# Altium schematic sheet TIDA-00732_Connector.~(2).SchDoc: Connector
size 431 x 279 mm; Date: Not shown in title block; ApprovedBy: Not shown in title block; CheckedBy: Not shown in title block; Author: Not shown in title block; CompanyName: Not shown in title block; DrawnBy: Anbu Mani; Engineer: Not shown in title block; Organization: Not shown in title block; Address1: Not shown in title block; Address2: Not shown in title block; Address3: Not shown in title block; Address4: Not shown in title block; DocumentNumber: 1; Revision: Use project parameter SCH_Rev; SheetNumber: 2; SheetTotal: 10; PageSetup: Record=PageOptions¦CenterHorizontal=True¦CenterVertical=True¦PrintScale=1.00¦XCorrection=1.00¦YCorrection=1.00¦PrintKind=0¦BorderSize=5000000¦LeftOffset=0¦BottomOffset=0¦Orientation=2¦PaperLength=1000¦PaperWidth=1000¦Scale=100¦PaperSource=15¦PrintQuality=600¦MediaType=1¦DitherType=10¦PaperKind=Letter¦PrintScaleMode=1
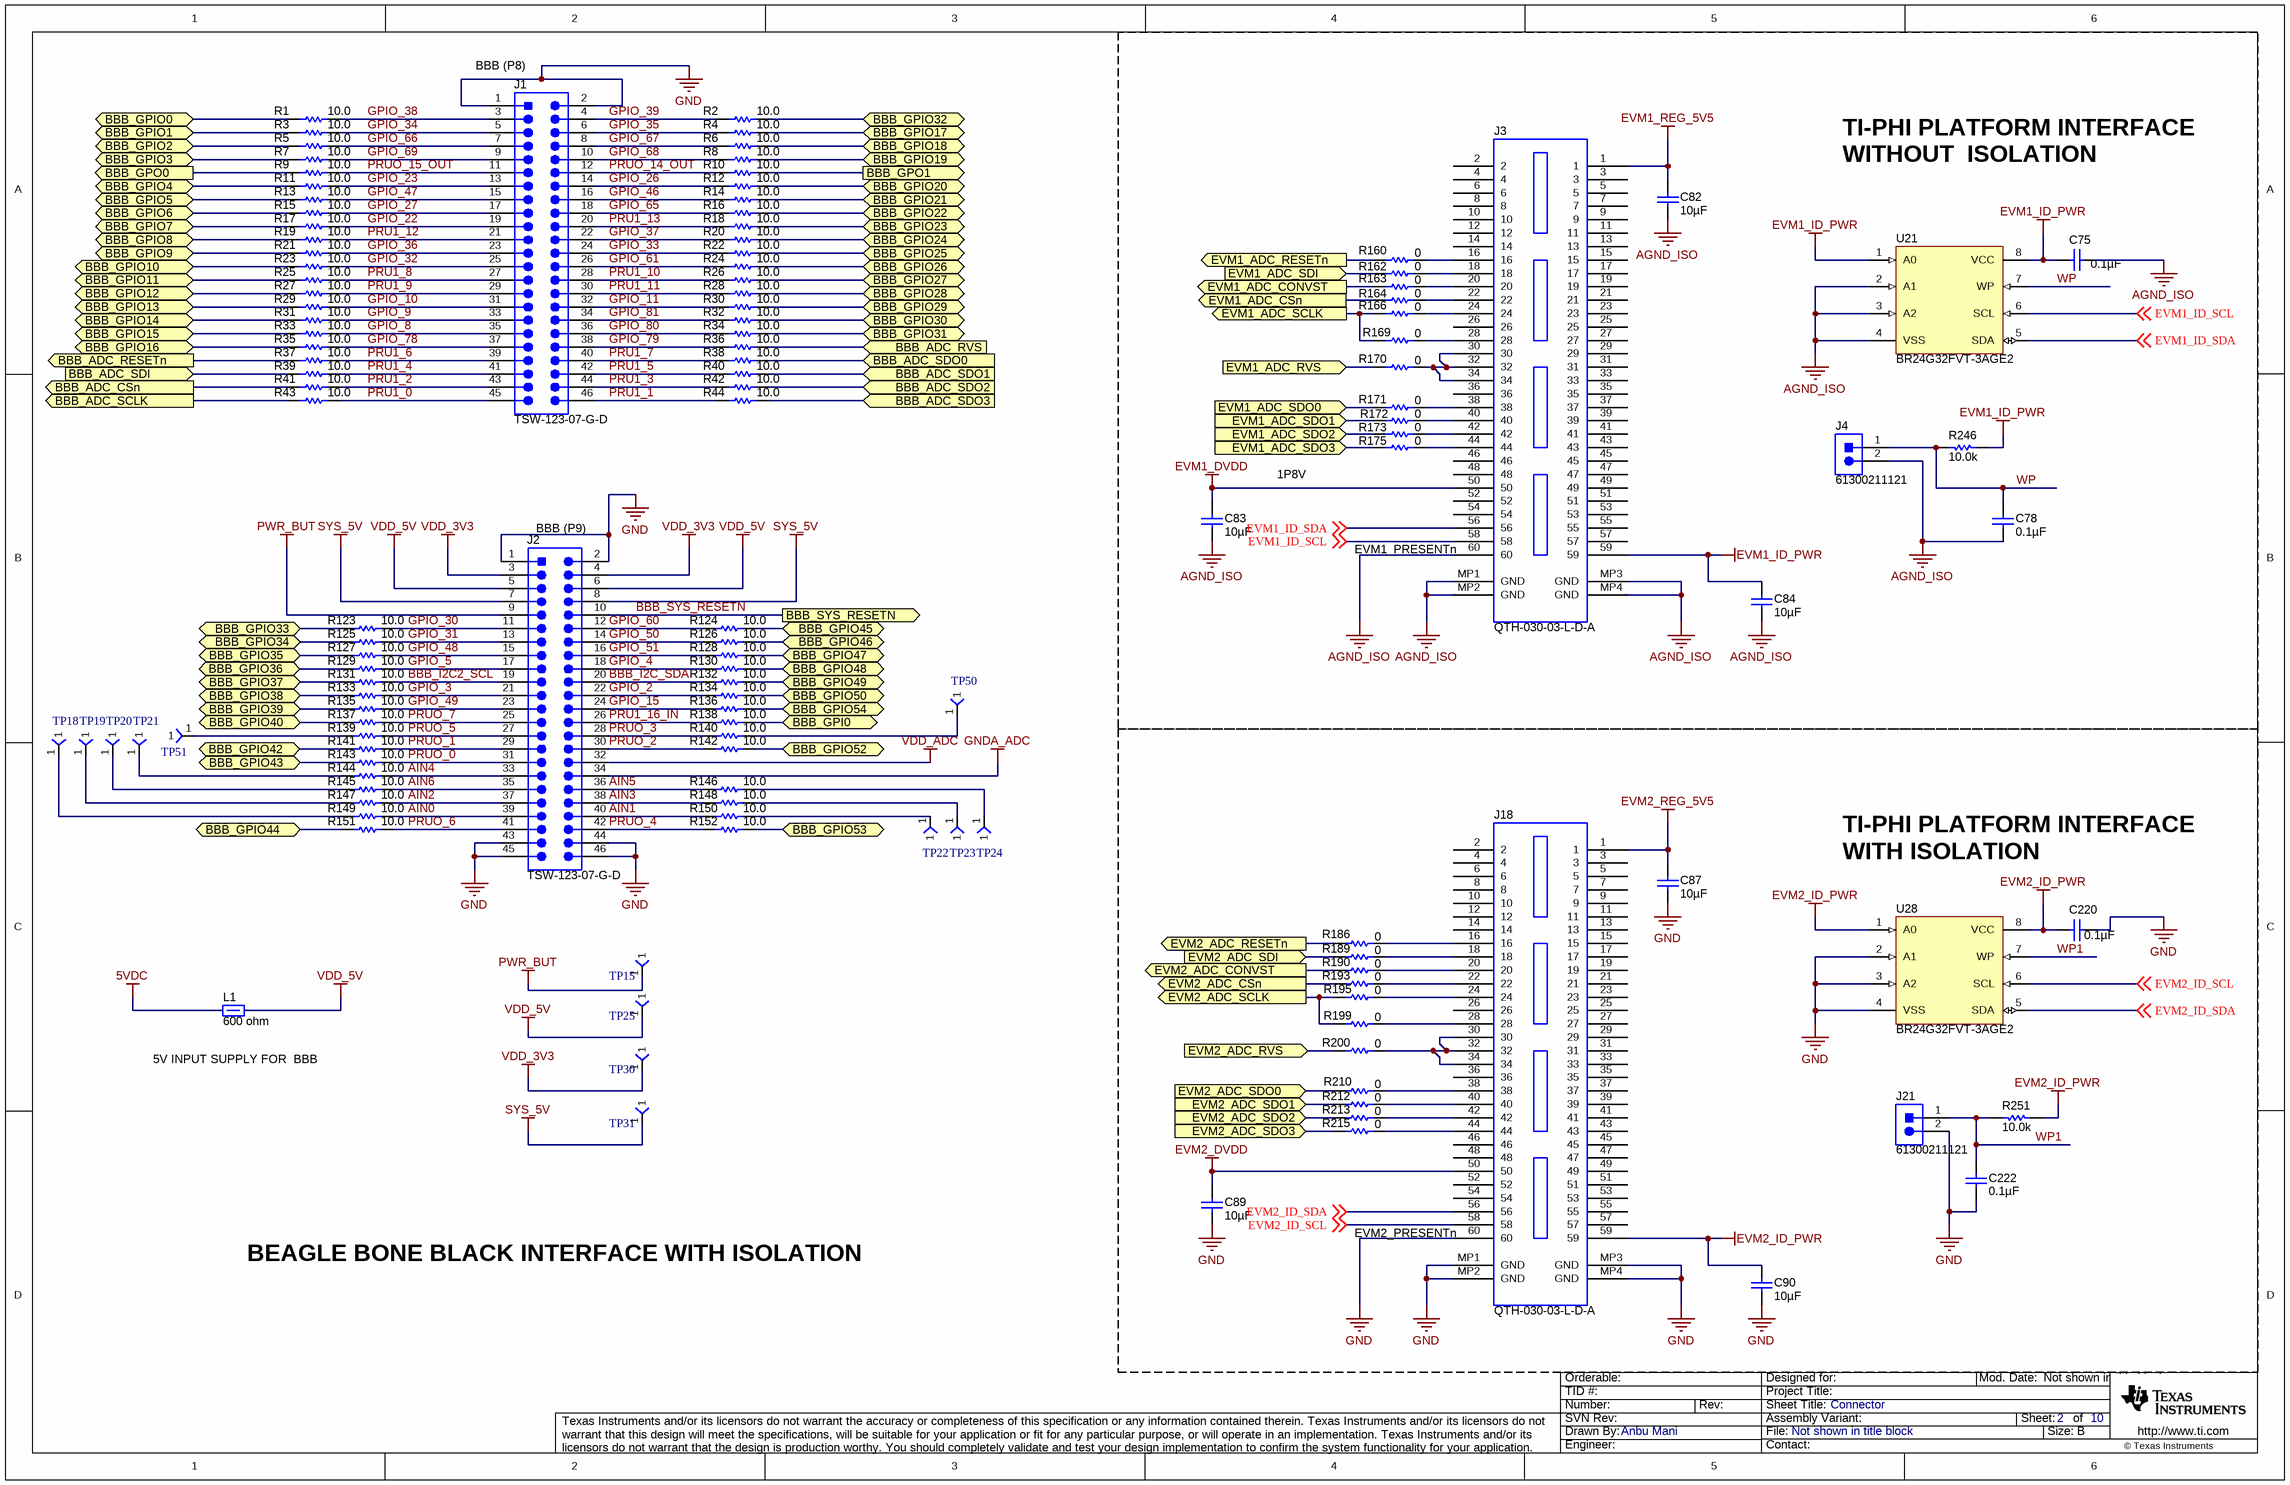
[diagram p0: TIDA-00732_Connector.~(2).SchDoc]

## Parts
C75  ValueDisplayed: 0.1µF  [0402]  (hidden comment: GRM155R71C104KA88D)
C78  ValueDisplayed: 0.1µF  [0402]  (hidden comment: GRM155R71C104KA88D)
C82  ValueDisplayed: 10µF  [0805_HV]  (hidden comment: GRM21BR71A106KE51L)
C83  ValueDisplayed: 10µF  [0805_HV]  (hidden comment: GRM21BR71A106KE51L)
C84  ValueDisplayed: 10µF  [0805_HV]  (hidden comment: GRM21BR71A106KE51L)
C87  ValueDisplayed: 10µF  [0805_HV]  (hidden comment: GRM21BR71A106KE51L)
C89  ValueDisplayed: 10µF  [0805_HV]  (hidden comment: GRM21BR71A106KE51L)
C90  ValueDisplayed: 10µF  [0805_HV]  (hidden comment: GRM21BR71A106KE51L)
C220  ValueDisplayed: 0.1µF  [0402]  (hidden comment: GRM155R71C104KA88D)
C222  ValueDisplayed: 0.1µF  [0402]  (hidden comment: GRM155R71C104KA88D)
J1  TSW-123-07-G-D  [Samtec_TSW-123-07-x-D]
J2  TSW-123-07-G-D  [Samtec_TSW-123-07-x-D]
J3  QTH-030-03-L-D-A  [Samtec_QTH-030-01-x-D-A]
J4  61300211121  [WURTH_61300211121]
J18  QTH-030-03-L-D-A  [Samtec_QTH-030-01-x-D-A]
J21  61300211121  [WURTH_61300211121]
L1  value 600 ohm  [0805_HV]  (hidden comment: HZ0805E601R-10)
R1  ValueDisplayed: 10.0  [0402]  (hidden comment: CRCW040210R0FKED)
R2  ValueDisplayed: 10.0  [0402]  (hidden comment: CRCW040210R0FKED)
R3  ValueDisplayed: 10.0  [0402]  (hidden comment: CRCW040210R0FKED)
R4  ValueDisplayed: 10.0  [0402]  (hidden comment: CRCW040210R0FKED)
R5  ValueDisplayed: 10.0  [0402]  (hidden comment: CRCW040210R0FKED)
R6  ValueDisplayed: 10.0  [0402]  (hidden comment: CRCW040210R0FKED)
R7  ValueDisplayed: 10.0  [0402]  (hidden comment: CRCW040210R0FKED)
R8  ValueDisplayed: 10.0  [0402]  (hidden comment: CRCW040210R0FKED)
R9  ValueDisplayed: 10.0  [0402]  (hidden comment: CRCW040210R0FKED)
R10  ValueDisplayed: 10.0  [0402]  (hidden comment: CRCW040210R0FKED)
R11  ValueDisplayed: 10.0  [0402]  (hidden comment: CRCW040210R0FKED)
R12  ValueDisplayed: 10.0  [0402]  (hidden comment: CRCW040210R0FKED)
R13  ValueDisplayed: 10.0  [0402]  (hidden comment: CRCW040210R0FKED)
R14  ValueDisplayed: 10.0  [0402]  (hidden comment: CRCW040210R0FKED)
R15  ValueDisplayed: 10.0  [0402]  (hidden comment: CRCW040210R0FKED)
R16  ValueDisplayed: 10.0  [0402]  (hidden comment: CRCW040210R0FKED)
R17  ValueDisplayed: 10.0  [0402]  (hidden comment: CRCW040210R0FKED)
R18  ValueDisplayed: 10.0  [0402]  (hidden comment: CRCW040210R0FKED)
R19  ValueDisplayed: 10.0  [0402]  (hidden comment: CRCW040210R0FKED)
R20  ValueDisplayed: 10.0  [0402]  (hidden comment: CRCW040210R0FKED)
R21  ValueDisplayed: 10.0  [0402]  (hidden comment: CRCW040210R0FKED)
R22  ValueDisplayed: 10.0  [0402]  (hidden comment: CRCW040210R0FKED)
R23  ValueDisplayed: 10.0  [0402]  (hidden comment: CRCW040210R0FKED)
R24  ValueDisplayed: 10.0  [0402]  (hidden comment: CRCW040210R0FKED)
R25  ValueDisplayed: 10.0  [0402]  (hidden comment: CRCW040210R0FKED)
R26  ValueDisplayed: 10.0  [0402]  (hidden comment: CRCW040210R0FKED)
R27  ValueDisplayed: 10.0  [0402]  (hidden comment: CRCW040210R0FKED)
R28  ValueDisplayed: 10.0  [0402]  (hidden comment: CRCW040210R0FKED)
R29  ValueDisplayed: 10.0  [0402]  (hidden comment: CRCW040210R0FKED)
R30  ValueDisplayed: 10.0  [0402]  (hidden comment: CRCW040210R0FKED)
R31  ValueDisplayed: 10.0  [0402]  (hidden comment: CRCW040210R0FKED)
R32  ValueDisplayed: 10.0  [0402]  (hidden comment: CRCW040210R0FKED)
R33  ValueDisplayed: 10.0  [0402]  (hidden comment: CRCW040210R0FKED)
R34  ValueDisplayed: 10.0  [0402]  (hidden comment: CRCW040210R0FKED)
R35  ValueDisplayed: 10.0  [0402]  (hidden comment: CRCW040210R0FKED)
R36  ValueDisplayed: 10.0  [0402]  (hidden comment: CRCW040210R0FKED)
R37  ValueDisplayed: 10.0  [0402]  (hidden comment: CRCW040210R0FKED)
R38  ValueDisplayed: 10.0  [0402]  (hidden comment: CRCW040210R0FKED)
R39  ValueDisplayed: 10.0  [0402]  (hidden comment: CRCW040210R0FKED)
R40  ValueDisplayed: 10.0  [0402]  (hidden comment: CRCW040210R0FKED)
R41  ValueDisplayed: 10.0  [0402]  (hidden comment: CRCW040210R0FKED)
R42  ValueDisplayed: 10.0  [0402]  (hidden comment: CRCW040210R0FKED)
R43  ValueDisplayed: 10.0  [0402]  (hidden comment: CRCW040210R0FKED)
R44  ValueDisplayed: 10.0  [0402]  (hidden comment: CRCW040210R0FKED)
R123  ValueDisplayed: 10.0  [0402]  (hidden comment: CRCW040210R0FKED)
R124  ValueDisplayed: 10.0  [0402]  (hidden comment: CRCW040210R0FKED)
R125  ValueDisplayed: 10.0  [0402]  (hidden comment: CRCW040210R0FKED)
R126  ValueDisplayed: 10.0  [0402]  (hidden comment: CRCW040210R0FKED)
R127  ValueDisplayed: 10.0  [0402]  (hidden comment: CRCW040210R0FKED)
R128  ValueDisplayed: 10.0  [0402]  (hidden comment: CRCW040210R0FKED)
R129  ValueDisplayed: 10.0  [0402]  (hidden comment: CRCW040210R0FKED)
R130  ValueDisplayed: 10.0  [0402]  (hidden comment: CRCW040210R0FKED)
R131  ValueDisplayed: 10.0  [0402]  (hidden comment: CRCW040210R0FKED)
R132  ValueDisplayed: 10.0  [0402]  (hidden comment: CRCW040210R0FKED)
R133  ValueDisplayed: 10.0  [0402]  (hidden comment: CRCW040210R0FKED)
R134  ValueDisplayed: 10.0  [0402]  (hidden comment: CRCW040210R0FKED)
R135  ValueDisplayed: 10.0  [0402]  (hidden comment: CRCW040210R0FKED)
R136  ValueDisplayed: 10.0  [0402]  (hidden comment: CRCW040210R0FKED)
R137  ValueDisplayed: 10.0  [0402]  (hidden comment: CRCW040210R0FKED)
R138  ValueDisplayed: 10.0  [0402]  (hidden comment: CRCW040210R0FKED)
R139  ValueDisplayed: 10.0  [0402]  (hidden comment: CRCW040210R0FKED)
R140  ValueDisplayed: 10.0  [0402]  (hidden comment: CRCW040210R0FKED)
R141  ValueDisplayed: 10.0  [0402]  (hidden comment: CRCW040210R0FKED)
R142  ValueDisplayed: 10.0  [0402]  (hidden comment: CRCW040210R0FKED)
R143  ValueDisplayed: 10.0  [0402]  (hidden comment: CRCW040210R0FKED)
R144  ValueDisplayed: 10.0  [0402]  (hidden comment: CRCW040210R0FKED)
R145  ValueDisplayed: 10.0  [0402]  (hidden comment: CRCW040210R0FKED)
R146  ValueDisplayed: 10.0  [0402]  (hidden comment: CRCW040210R0FKED)
R147  ValueDisplayed: 10.0  [0402]  (hidden comment: CRCW040210R0FKED)
R148  ValueDisplayed: 10.0  [0402]  (hidden comment: CRCW040210R0FKED)
R149  ValueDisplayed: 10.0  [0402]  (hidden comment: CRCW040210R0FKED)
R150  ValueDisplayed: 10.0  [0402]  (hidden comment: CRCW040210R0FKED)
R151  ValueDisplayed: 10.0  [0402]  (hidden comment: CRCW040210R0FKED)
R152  ValueDisplayed: 10.0  [0402]  (hidden comment: CRCW040210R0FKED)
R160  ValueDisplayed: 0  [0402]  (hidden comment: ERJ-2GE0R00X)
R162  ValueDisplayed: 0  [0402]  (hidden comment: ERJ-2GE0R00X)
R163  ValueDisplayed: 0  [0402]  (hidden comment: ERJ-2GE0R00X)
R164  ValueDisplayed: 0  [0402]  (hidden comment: ERJ-2GE0R00X)
R166  ValueDisplayed: 0  [0402]  (hidden comment: ERJ-2GE0R00X)
R169  ValueDisplayed: 0  [0402]  (hidden comment: ERJ-2GE0R00X)
R170  ValueDisplayed: 0  [0402]  (hidden comment: ERJ-2GE0R00X)
R171  ValueDisplayed: 0  [0402]  (hidden comment: ERJ-2GE0R00X)
R172  ValueDisplayed: 0  [0402]  (hidden comment: ERJ-2GE0R00X)
R173  ValueDisplayed: 0  [0402]  (hidden comment: ERJ-2GE0R00X)
R175  ValueDisplayed: 0  [0402]  (hidden comment: ERJ-2GE0R00X)
R186  ValueDisplayed: 0  [0402]  (hidden comment: ERJ-2GE0R00X)
R189  ValueDisplayed: 0  [0402]  (hidden comment: ERJ-2GE0R00X)
R190  ValueDisplayed: 0  [0402]  (hidden comment: ERJ-2GE0R00X)
R193  ValueDisplayed: 0  [0402]  (hidden comment: ERJ-2GE0R00X)
R195  ValueDisplayed: 0  [0402]  (hidden comment: ERJ-2GE0R00X)
R199  ValueDisplayed: 0  [0402]  (hidden comment: ERJ-2GE0R00X)
R200  ValueDisplayed: 0  [0402]  (hidden comment: ERJ-2GE0R00X)
R210  ValueDisplayed: 0  [0402]  (hidden comment: ERJ-2GE0R00X)
R212  ValueDisplayed: 0  [0402]  (hidden comment: ERJ-2GE0R00X)
R213  ValueDisplayed: 0  [0402]  (hidden comment: ERJ-2GE0R00X)
R215  ValueDisplayed: 0  [0402]  (hidden comment: ERJ-2GE0R00X)
R246  ValueDisplayed: 10.0k  [0603]  (hidden comment: CRCW060310K0FKEA)
R251  ValueDisplayed: 10.0k  [0603]  (hidden comment: CRCW060310K0FKEA)
TP15  TP-025-SMT  [TP_25MIL-SMT]  (value not drawn)
TP18  TP-025-SMT  [TP_25MIL-SMT]  (value not drawn)
TP19  TP-025-SMT  [TP_25MIL-SMT]  (value not drawn)
TP20  TP-025-SMT  [TP_25MIL-SMT]  (value not drawn)
TP21  TP-025-SMT  [TP_25MIL-SMT]  (value not drawn)
TP22  TP-025-SMT  [TP_25MIL-SMT]  (value not drawn)
TP23  TP-025-SMT  [TP_25MIL-SMT]  (value not drawn)
TP24  TP-025-SMT  [TP_25MIL-SMT]  (value not drawn)
TP25  TP-025-SMT  [TP_25MIL-SMT]  (value not drawn)
TP30  TP-025-SMT  [TP_25MIL-SMT]  (value not drawn)
TP31  TP-025-SMT  [TP_25MIL-SMT]  (value not drawn)
TP50  TP-025-SMT  [TP_25MIL-SMT]  (value not drawn)
TP51  TP-025-SMT  [TP_25MIL-SMT]  (value not drawn)
U21  BR24G32FVT-3AGE2  [TSOP65P640X120-8N]
U28  BR24G32FVT-3AGE2  [TSOP65P640X120-8N]

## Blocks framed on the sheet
EVM2_PRESENTn: C87 C89 C90 C220 C222 J18 J21 R186 R189 R190 R193 R195 R199 R200 R210 R212 R213 R215 R251 U28

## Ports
BBB_ADC_CSn (out), BBB_ADC_RESETn (out), BBB_ADC_RVS (in), BBB_ADC_SCLK (out), BBB_ADC_SDI (in), BBB_ADC_SDO0 (in), BBB_ADC_SDO1 (in), BBB_ADC_SDO2 (in), BBB_ADC_SDO3 (in), BBB_GPI0 (bidir), BBB_GPIO0 (bidir), BBB_GPIO1 (bidir), BBB_GPIO2 (bidir), BBB_GPIO3 (bidir), BBB_GPIO4 (bidir), BBB_GPIO5 (bidir), BBB_GPIO6 (bidir), BBB_GPIO7 (bidir), BBB_GPIO8 (bidir), BBB_GPIO9 (bidir), BBB_GPIO10 (bidir), BBB_GPIO11 (bidir), BBB_GPIO12 (bidir), BBB_GPIO13 (bidir), BBB_GPIO14 (bidir), BBB_GPIO15 (bidir), BBB_GPIO16 (bidir), BBB_GPIO17 (bidir), BBB_GPIO18 (bidir), BBB_GPIO19 (bidir), BBB_GPIO20 (bidir), BBB_GPIO21 (bidir), BBB_GPIO22 (bidir), BBB_GPIO23 (bidir), BBB_GPIO24 (bidir), BBB_GPIO25 (bidir), BBB_GPIO26 (bidir), BBB_GPIO27 (bidir), BBB_GPIO28 (bidir), BBB_GPIO29 (bidir), BBB_GPIO30 (bidir), BBB_GPIO31 (bidir), BBB_GPIO32 (bidir), BBB_GPIO33 (bidir), BBB_GPIO34 (bidir), BBB_GPIO35 (bidir), BBB_GPIO36 (bidir), BBB_GPIO37 (bidir), BBB_GPIO38 (bidir), BBB_GPIO39 (bidir), BBB_GPIO40 (bidir), BBB_GPIO42 (bidir), BBB_GPIO43 (bidir), BBB_GPIO44 (bidir), BBB_GPIO45 (bidir), BBB_GPIO46 (bidir), BBB_GPIO47 (bidir), BBB_GPIO48 (bidir), BBB_GPIO49 (bidir), BBB_GPIO50 (bidir), BBB_GPIO52 (bidir), BBB_GPIO53 (bidir), BBB_GPIO54 (bidir), BBB_GPO0 (out), BBB_GPO1 (out), BBB_SYS_RESETN (out), EVM1_ADC_CONVST (out), EVM1_ADC_CSn (out), EVM1_ADC_RESETn (out), EVM1_ADC_RVS (in), EVM1_ADC_SCLK (out), EVM1_ADC_SDI (in), EVM1_ADC_SDO0 (in), EVM1_ADC_SDO1 (in), EVM1_ADC_SDO2 (in), EVM1_ADC_SDO3 (in), EVM2_ADC_CONVST (out), EVM2_ADC_CSn (out), EVM2_ADC_RESETn (out), EVM2_ADC_RVS (in), EVM2_ADC_SCLK (out), EVM2_ADC_SDI (in), EVM2_ADC_SDO0 (in), EVM2_ADC_SDO1 (in), EVM2_ADC_SDO2 (in), EVM2_ADC_SDO3 (in)

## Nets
5VDC: L1.1
AGND_ISO: C75.1 C78.1 C82.2 C83.2 C84.2 J3.60 J3.MP1(GND) J3.MP2(GND) J3.MP3(GND) J3.MP4(GND) J4.2 U21.2(A1) U21.3(A2) U21.4(VSS)
EVM1_DVDD: C83.1 J3.50
EVM1_ID_PWR: C75.2 C84.1 J3.59 R246.2 U21.1(A0) U21.8(VCC)
EVM1_REG_5V5: C82.1 J3.1
EVM2_DVDD: C89.1 J18.50
EVM2_ID_PWR: C90.1 C220.2 J18.59 R251.2 U28.1(A0) U28.8(VCC)
EVM2_REG_5V5: C87.1 J18.1
GND: C87.2 C89.2 C90.2 C220.1 C222.1 J1.1 J1.2 J2.1 J2.2 J2.43 J2.44 J2.45 J2.46 J18.60 J18.MP1(GND) J18.MP2(GND) J18.MP3(GND) J18.MP4(GND) J21.2 U28.2(A1) U28.3(A2) U28.4(VSS)
GNDA_ADC: J2.34
PWR_BUT: J2.9 TP15.1
SYS_5V: J2.7 J2.8 TP31.1
VDD_3V3: J2.3 J2.4 TP30.1
VDD_5V: J2.5 J2.6 L1.2 TP25.1
VDD_ADC: J2.32
AIN0: J2.39 R149.2
AIN1: J2.40 R150.1
AIN2: J2.37 R147.2
AIN3: J2.38 R148.1
AIN4: J2.33 R144.2
AIN5: J2.36 R146.1
AIN6: J2.35 R145.2
BBB_ADC_CSn: R41.1 ; port BBB_ADC_CSn
BBB_ADC_RESETn: R37.1 ; port BBB_ADC_RESETn
BBB_ADC_RVS: R36.2 ; port BBB_ADC_RVS
BBB_ADC_SCLK: R43.1 ; port BBB_ADC_SCLK
BBB_ADC_SDI: R39.1 ; port BBB_ADC_SDI
BBB_ADC_SDO0: R38.2 ; port BBB_ADC_SDO0
BBB_ADC_SDO1: R40.2 ; port BBB_ADC_SDO1
BBB_ADC_SDO2: R42.2 ; port BBB_ADC_SDO2
BBB_ADC_SDO3: R44.2 ; port BBB_ADC_SDO3
BBB_GPI0: R138.2 ; port BBB_GPI0
BBB_GPIO0: R1.1 ; port BBB_GPIO0
BBB_GPIO1: R3.1 ; port BBB_GPIO1
BBB_GPIO2: R5.1 ; port BBB_GPIO2
BBB_GPIO3: R7.1 ; port BBB_GPIO3
BBB_GPIO4: R11.1 ; port BBB_GPIO4
BBB_GPIO5: R13.1 ; port BBB_GPIO5
BBB_GPIO6: R15.1 ; port BBB_GPIO6
BBB_GPIO7: R17.1 ; port BBB_GPIO7
BBB_GPIO8: R19.1 ; port BBB_GPIO8
BBB_GPIO9: R21.1 ; port BBB_GPIO9
BBB_GPIO10: R23.1 ; port BBB_GPIO10
BBB_GPIO11: R25.1 ; port BBB_GPIO11
BBB_GPIO12: R27.1 ; port BBB_GPIO12
BBB_GPIO13: R29.1 ; port BBB_GPIO13
BBB_GPIO14: R31.1 ; port BBB_GPIO14
BBB_GPIO15: R33.1 ; port BBB_GPIO15
BBB_GPIO16: R35.1 ; port BBB_GPIO16
BBB_GPIO17: R4.2 ; port BBB_GPIO17
BBB_GPIO18: R6.2 ; port BBB_GPIO18
BBB_GPIO19: R8.2 ; port BBB_GPIO19
BBB_GPIO20: R12.2 ; port BBB_GPIO20
BBB_GPIO21: R14.2 ; port BBB_GPIO21
BBB_GPIO22: R16.2 ; port BBB_GPIO22
BBB_GPIO23: R18.2 ; port BBB_GPIO23
BBB_GPIO24: R20.2 ; port BBB_GPIO24
BBB_GPIO25: R22.2 ; port BBB_GPIO25
BBB_GPIO26: R24.2 ; port BBB_GPIO26
BBB_GPIO27: R26.2 ; port BBB_GPIO27
BBB_GPIO28: R28.2 ; port BBB_GPIO28
BBB_GPIO29: R30.2 ; port BBB_GPIO29
BBB_GPIO30: R32.2 ; port BBB_GPIO30
BBB_GPIO31: R34.2 ; port BBB_GPIO31
BBB_GPIO32: R2.2 ; port BBB_GPIO32
BBB_GPIO33: R123.1 ; port BBB_GPIO33
BBB_GPIO34: R125.1 ; port BBB_GPIO34
BBB_GPIO35: R127.1 ; port BBB_GPIO35
BBB_GPIO36: R129.1 ; port BBB_GPIO36
BBB_GPIO37: R131.1 ; port BBB_GPIO37
BBB_GPIO38: R133.1 ; port BBB_GPIO38
BBB_GPIO39: R135.1 ; port BBB_GPIO39
BBB_GPIO40: R137.1 ; port BBB_GPIO40
BBB_GPIO42: R141.1 ; port BBB_GPIO42
BBB_GPIO43: R143.1 ; port BBB_GPIO43
BBB_GPIO44: R151.1 ; port BBB_GPIO44
BBB_GPIO45: R124.2 ; port BBB_GPIO45
BBB_GPIO46: R126.2 ; port BBB_GPIO46
BBB_GPIO47: R128.2 ; port BBB_GPIO47
BBB_GPIO48: R130.2 ; port BBB_GPIO48
BBB_GPIO49: R132.2 ; port BBB_GPIO49
BBB_GPIO50: R134.2 ; port BBB_GPIO50
BBB_GPIO52: R142.2 ; port BBB_GPIO52
BBB_GPIO53: R152.2 ; port BBB_GPIO53
BBB_GPIO54: R136.2 ; port BBB_GPIO54
BBB_GPO0: R9.1 ; port BBB_GPO0
BBB_GPO1: R10.2 ; port BBB_GPO1
BBB_I2C2_SCL: J2.19 R131.2
BBB_I2C_SDA: J2.20 R132.1
BBB_SYS_RESETN: J2.10 ; port BBB_SYS_RESETN
EVM1_ADC_CONVST: R163.1 ; port EVM1_ADC_CONVST
EVM1_ADC_CSn: R164.1 ; port EVM1_ADC_CSn
EVM1_ADC_RESETn: R160.1 ; port EVM1_ADC_RESETn
EVM1_ADC_RVS: R170.1 ; port EVM1_ADC_RVS
EVM1_ADC_SCLK: R166.1 R169.1 ; port EVM1_ADC_SCLK
EVM1_ADC_SDI: R162.1 ; port EVM1_ADC_SDI
EVM1_ADC_SDO0: R171.1 ; port EVM1_ADC_SDO0
EVM1_ADC_SDO1: R172.1 ; port EVM1_ADC_SDO1
EVM1_ADC_SDO2: R173.1 ; port EVM1_ADC_SDO2
EVM1_ADC_SDO3: R175.1 ; port EVM1_ADC_SDO3
EVM1_ID_SCL: J3.58 U21.6(SCL) ; off-sheet EVM1_ID_SCL
EVM1_ID_SDA: J3.56 U21.5(SDA) ; off-sheet EVM1_ID_SDA
EVM2_ADC_CONVST: R190.1 ; port EVM2_ADC_CONVST
EVM2_ADC_CSn: R193.1 ; port EVM2_ADC_CSn
EVM2_ADC_RESETn: R186.1 ; port EVM2_ADC_RESETn
EVM2_ADC_RVS: R200.1 ; port EVM2_ADC_RVS
EVM2_ADC_SCLK: R195.1 R199.1 ; port EVM2_ADC_SCLK
EVM2_ADC_SDI: R189.1 ; port EVM2_ADC_SDI
EVM2_ADC_SDO0: R210.1 ; port EVM2_ADC_SDO0
EVM2_ADC_SDO1: R212.1 ; port EVM2_ADC_SDO1
EVM2_ADC_SDO2: R213.1 ; port EVM2_ADC_SDO2
EVM2_ADC_SDO3: R215.1 ; port EVM2_ADC_SDO3
EVM2_ID_SCL: J18.58 U28.6(SCL) ; off-sheet EVM2_ID_SCL
EVM2_ID_SDA: J18.56 U28.5(SDA) ; off-sheet EVM2_ID_SDA
GPIO_2: J2.22 R134.1
GPIO_3: J2.21 R133.2
GPIO_4: J2.18 R130.1
GPIO_5: J2.17 R129.2
GPIO_8: J1.35 R33.2
GPIO_9: J1.33 R31.2
GPIO_10: J1.31 R29.2
GPIO_11: J1.32 R30.1
GPIO_15: J2.24 R136.1
GPIO_22: J1.19 R17.2
GPIO_23: J1.13 R11.2
GPIO_26: J1.14 R12.1
GPIO_27: J1.17 R15.2
GPIO_30: J2.11 R123.2
GPIO_31: J2.13 R125.2
GPIO_32: J1.25 R23.2
GPIO_33: J1.24 R22.1
GPIO_34: J1.5 R3.2
GPIO_35: J1.6 R4.1
GPIO_36: J1.23 R21.2
GPIO_37: J1.22 R20.1
GPIO_38: J1.3 R1.2
GPIO_39: J1.4 R2.1
GPIO_46: J1.16 R14.1
GPIO_47: J1.15 R13.2
GPIO_48: J2.15 R127.2
GPIO_49: J2.23 R135.2
GPIO_50: J2.14 R126.1
GPIO_51: J2.16 R128.1
GPIO_60: J2.12 R124.1
GPIO_61: J1.26 R24.1
GPIO_65: J1.18 R16.1
GPIO_66: J1.7 R5.2
GPIO_67: J1.8 R6.1
GPIO_68: J1.10 R8.1
GPIO_69: J1.9 R7.2
GPIO_78: J1.37 R35.2
GPIO_79: J1.38 R36.1
GPIO_80: J1.36 R34.1
GPIO_81: J1.34 R32.1
PRU1_0: J1.45 R43.2
PRU1_1: J1.46 R44.1
PRU1_2: J1.43 R41.2
PRU1_3: J1.44 R42.1
PRU1_4: J1.41 R39.2
PRU1_5: J1.42 R40.1
PRU1_6: J1.39 R37.2
PRU1_7: J1.40 R38.1
PRU1_8: J1.27 R25.2
PRU1_9: J1.29 R27.2
PRU1_10: J1.28 R26.1
PRU1_11: J1.30 R28.1
PRU1_12: J1.21 R19.2
PRU1_13: J1.20 R18.1
PRU1_16_IN: J2.26 R138.1
PRUO_0: J2.31 R143.2
PRUO_1: J2.29 R141.2
PRUO_2: J2.30 R142.1
PRUO_3: J2.28 R140.1
PRUO_4: J2.42 R152.1
PRUO_5: J2.27 R139.2
PRUO_6: J2.41 R151.2
PRUO_7: J2.25 R137.2
PRUO_14_OUT: J1.12 R10.1
PRUO_15_OUT: J1.11 R9.2
WP: C78.2 J4.1 R246.1 U21.7(WP)
WP1: C222.2 J21.1 R251.1 U28.7(WP)
NetJ3_16: J3.16 R160.2
NetJ3_18: J3.18 R162.2
NetJ3_20: J3.20 R163.2
NetJ3_22: J3.22 R164.2
NetJ3_24: J3.24 R166.2
NetJ3_28: J3.28 R169.2
NetJ3_30: J3.30 J3.32 J3.34 R170.2
NetJ3_38: J3.38 R171.2
NetJ3_40: J3.40 R172.2
NetJ3_42: J3.42 R173.2
NetJ3_44: J3.44 R175.2
NetJ18_16: J18.16 R186.2
NetJ18_18: J18.18 R189.2
NetJ18_20: J18.20 R190.2
NetJ18_22: J18.22 R193.2
NetJ18_24: J18.24 R195.2
NetJ18_28: J18.28 R199.2
NetJ18_30: J18.30 J18.32 J18.34 R200.2
NetJ18_38: J18.38 R210.2
NetJ18_40: J18.40 R212.2
NetJ18_42: J18.42 R213.2
NetJ18_44: J18.44 R215.2
NetR139_1: R139.1 TP51.1
NetR140_2: R140.2 TP50.1
NetR144_1: R144.1 TP21.1
NetR145_1: R145.1 TP20.1
NetR146_2: R146.2 TP24.1
NetR147_1: R147.1 TP19.1
NetR148_2: R148.2 TP23.1
NetR149_1: R149.1 TP18.1
NetR150_2: R150.2 TP22.1

Not connected (* = marked no-connect by the designer): J3 2 3 4 5 6 7 8 9 10 11 12 13 14 15 17 19 21 23 25 26 27 29 31 33 35 36 37 39 41 43 45 46 47 48 49 51 52 53 54 55 57; J18 2 3 4 5 6 7 8 9 10 11 12 13 14 15 17 19 21 23 25 26 27 29 31 33 35 36 37 39 41 43 45 46 47 48 49 51 52 53 54 55 57

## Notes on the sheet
- (near J1) BBB (P8)
- TI-PHI PLATFORM INTERFACE
  WITHOUT  ISOLATION
- 1P8V
- (near J2) BBB (P9)
- (near J3) EVM1_PRESENTn
- TI-PHI PLATFORM INTERFACE WITH ISOLATION
- (near L1) 5V INPUT SUPPLY FOR  BBB
- BEAGLE BONE BLACK INTERFACE WITH ISOLATION

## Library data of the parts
C75 C78 C220 C222 = GRM155R71C104KA88D: CAP, CERM, 0.1 µF, 16 V, +/- 10%, X7R, 0402; Manufacturer: MuRata; Polarized: N; CompType: Capacitor; Value: 0.1uF; U/M: EA; Cap_F: 0.0000001; Tolerance_%: 10; Value1: Unknown; VDC_V: 16; Value2: 16V; TaMin_C: -55; TaMax_C: 125
C82-C84 C87 C89 C90 = GRM21BR71A106KE51L: CAP, CERM, 10 µF, 10 V, +/- 10%, X7R, 0805; Manufacturer: MuRata; Polarized: N; CompType: Capacitor; Value: 10uF; U/M: EA; Cap_F: 0.00001; Tolerance_%: 10; ESR_ohm: 0.003; Value1: 0.003 ohm; Value2: 10V; TaMin_C: -55; TaMax_C: 125; Cap_Case: 0805; AEC Category: Q200
J1 J2 = TSW-123-07-G-D: Header, 2.54 mm, 23x2, Gold, TH; Manufacturer: Samtec; SymbolCreator: Altium; U/M: EA
J3 J18 = QTH-030-01-L-D-A: Header(Shrouded), 19.7mil, 30x2, Gold, SMT; Manufacturer: Samtec; SymbolCreator: Altium; U/M: EA
J4 J21 = 61300211121: Header, 2.54 mm, 2x1, Gold, TH; Manufacturer: Wurth Elektronik eiSos; SymbolCreator: a0412235; U/M: EA
L1 = HZ0805E601R-10: Ferrite Bead, 600 ohm @ 100 MHz, 0.5 A, 0805; Manufacturer: Laird-Signal Integrity Products; Imax_A: 0.5; DCR_ohm: 0.3; Value1: 0.3 ohm; Value2: 0.5A; ZTyp@100MHz_Ohm: 600
R1-R44 R123-R152 = CRCW040210R0FKED: RES, 10.0, 1%, 0.063 W, 0402; Manufacturer: Vishay-Dale; CompType: Resistor; Value: 10.0; Res_ohm: 10; Value_Code: 10R0; Tolerance_%: 1; Power_W: 0.063; Value2: 0.063W; VDC_V: 50; TempCo: 100 ppm/C; EIA_Code: E96; U/M: EA
R160 R162-R164 R166 R169-R173 R175 R186 R189 R190 R193 R195 R199 R200 R210 R212 R213 R215 = ERJ-2GE0R00X: RES, 0, 5%, 0.063 W, 0402; Manufacturer: Panasonic; CompType: Resistor; Value: 0; Value_Code: 0000; Tolerance_%: 5; Power_W: 0.063; Value2: 0.063W; VDC_V: 50; TempCo: 600 ppm/C; EIA_Code: E24; U/M: EA; AEC Category: Q200
R246 R251 = CRCW060310K0FKEA: RES, 10.0 k, 1%, 0.1 W, 0603; Manufacturer: Vishay-Dale; CompType: Resistor; Value: 10.0k; Res_ohm: 10000; Value_Code: 10k0; Tolerance_%: 1; Power_W: 0.1; Value2: 0.1W; VDC_V: 75; TempCo: 100 ppm/C; EIA_Code: E96; U/M: EA
TP15 TP18-TP25 TP30 TP31 TP50 TP51 = TP-025-SMT: Test Point, O.025"; Manufacturer: STD; Value: STD
U21 U28 = BR24G32FVT-3AGE2: I2C BUS EEPROM (2-Wire), TSSOP-B8; Manufacturer: Rohm; SymbolCreator: a0411947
